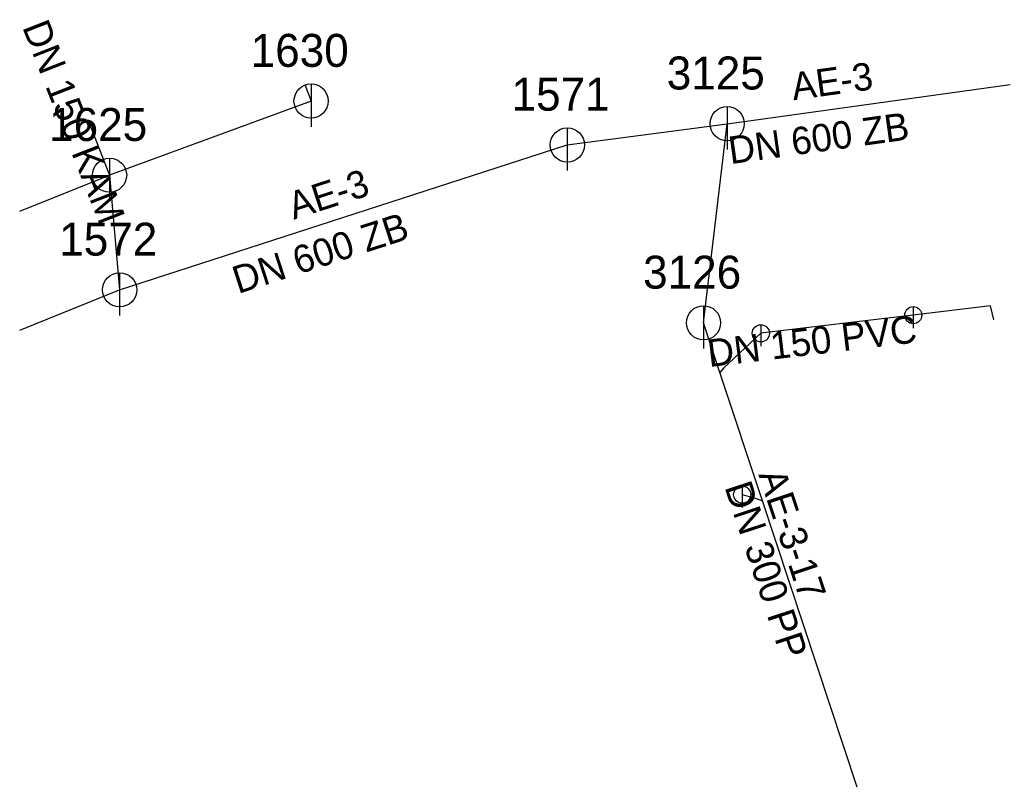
# Model space of a CAD drawing. Extents: x -494060.6 to -494002.7, y -1126804.1 to -1126759.3.
import ezdxf

# ---------------------------------------------------------------- set-up
doc = ezdxf.new("R2010")
doc.units = 0
for name, color, linetype in [('_pripojka_kanal_jednotna_priblizne_', 7, 'Continuous'), ('_pripojka_kanal_splaskova_prevzato_z_dokumentace_', 7, 'Continuous'), ('_pripojka_kanal_splaskova_priblizne_', 7, 'Continuous'), ('_stoka_jednotna_smvak_prevzato_z_dokumentace_', 7, 'Continuous'), ('_stoka_splaskova_provozovana_prevzato_z_dokumentace_', 7, 'Continuous'), ('Default', 7, 'Continuous'), ('MoLevel 119', 7, 'Continuous'), ('MoLevel 120', 7, 'Continuous'), ('MoLevel 124', 7, 'Continuous'), ('MoLevel 57', 7, 'Continuous'), ('MoLevel 60', 7, 'Continuous'), ('MoLevel 68', 7, 'Continuous'), ('MoLevel 69', 7, 'Continuous'), ('MoLevel 84', 7, 'Continuous'), ('MoLevel 85', 7, 'Continuous')]:
    doc.layers.add(name, color=color, linetype=linetype)

# ---------------------------------------------------------------- blocks, each defined once
blk = doc.blocks.new('_sachta_kanal_prip_')
at = {"layer": 'Default'}
blk.add_line((0, 0.00005), (0, -0.000075), dxfattribs=at)
blk.add_circle((0, 0), 0.00005, dxfattribs=at)
blk = doc.blocks.new('_sachta_kanal_prevzato_z_dokumentace_')
at = {"layer": 'Default'}
blk.add_line((0, 0.00005), (0, -0.000075), dxfattribs=at)
blk.add_circle((0, 0), 0.00005, dxfattribs=at)

msp = doc.modelspace()

# ---------------------------------------------------------------- linework, layer by layer
at = {"layer": '_pripojka_kanal_jednotna_priblizne_'}
for p, q in [((-494043.939, -1126763.067), (-494043.575, -1126764.029)), ((-494056.524, -1126765.36), (-494055.35, -1126768.36))]:
    msp.add_line(p, q, dxfattribs=at)
at = {"layer": '_pripojka_kanal_splaskova_prevzato_z_dokumentace_'}
for points in [[(-494017.3, -1126777.6), (-494019.47, -1126779.61), (-494019.692, -1126779.889)], [(-494018.39, -1126787.03), (-494017.57, -1126787.26), (-494017.213, -1126787.387)]]:
    msp.add_lwpolyline(points, dxfattribs=at)
at = {"layer": '_pripojka_kanal_splaskova_priblizne_'}
msp.add_line((-494008.399, -1126776.542), (-494017.3, -1126777.6), dxfattribs=at)
msp.add_lwpolyline([(-494003.685, -1126776.804), (-494003.878, -1126776.005), (-494008.399, -1126776.542)], dxfattribs=at)
at = {"layer": '_stoka_jednotna_smvak_prevzato_z_dokumentace_'}
for p, q in [((-494019.27, -1126765.35), (-494002.736, -1126763.056)), ((-494043.575, -1126764.029), (-494055.35, -1126768.36)), ((-494028.61, -1126766.59), (-494019.27, -1126765.35)), ((-494054.76, -1126775.06), (-494028.61, -1126766.59)), ((-494060.593, -1126770.47), (-494055.35, -1126768.36)), ((-494055.35, -1126768.36), (-494054.76, -1126775.06)), ((-494060.593, -1126777.424), (-494054.76, -1126775.06))]:
    msp.add_line(p, q, dxfattribs=at)
at = {"layer": '_stoka_splaskova_provozovana_prevzato_z_dokumentace_'}
msp.add_line((-494020.65, -1126776.99), (-494019.27, -1126765.35), dxfattribs=at)
msp.add_lwpolyline([(-494011.679, -1126804.129), (-494017.213, -1126787.387), (-494019.692, -1126779.889), (-494020.65, -1126776.99)], dxfattribs=at)

# ---------------------------------------------------------------- block references
at = {"layer": 'MoLevel 119', "xscale": 20000, "yscale": 20000}
for p in [(-494043.575, -1126764.029), (-494019.27, -1126765.35), (-494028.61, -1126766.59), (-494055.35, -1126768.36), (-494054.76, -1126775.06), (-494020.65, -1126776.99)]:
    msp.add_blockref('_sachta_kanal_prevzato_z_dokumentace_', p, dxfattribs=at)
at = {"layer": 'MoLevel 57', "xscale": 10000, "yscale": 10000}
for p in [(-494008.399, -1126776.542), (-494017.3, -1126777.6), (-494018.39, -1126787.03)]:
    msp.add_blockref('_sachta_kanal_prip_', p, dxfattribs=at)

# ---------------------------------------------------------------- texts
at = {"layer": 'MoLevel 120'}
for s, p in [('1630', (-494047.106, -1126762.029)), ('3125', (-494022.801, -1126763.35)), ('1571', (-494031.866, -1126764.59)), ('1625', (-494058.881, -1126766.36)), ('1572', (-494058.291, -1126773.06)), ('3126', (-494024.181, -1126774.99))]:
    msp.add_text(s, height=1.9259, dxfattribs=at).set_placement(p)
at = {"layer": 'MoLevel 124'}
msp.add_text('DN 150 KAM', height=1.6049, rotation=291.37937, dxfattribs=at).set_placement((-494060.464, -1126759.699))
at = {"layer": 'MoLevel 60'}
msp.add_text('DN 150 PVC', height=1.6049, rotation=6.77525, dxfattribs=at).set_placement((-494020.324, -1126779.575))
at = {"layer": 'MoLevel 68'}
for rotation, p in [(7.89772, (-494019.076, -1126767.716)), (17.94717, (-494047.843, -1126775.307))]:
    msp.add_text('DN 600 ZB', height=1.6049, rotation=rotation, dxfattribs=at).set_placement(p)
at = {"layer": 'MoLevel 69'}
for rotation, p in [(7.89772, (-494015.398, -1126763.985)), (17.94717, (-494044.593, -1126770.967))]:
    msp.add_text('AE-3', height=1.6049, rotation=rotation, dxfattribs=at).set_placement(p)
at = {"layer": 'MoLevel 84'}
msp.add_text('DN 300 PP', height=1.6049, rotation=288.29121, dxfattribs=at).set_placement((-494019.436, -1126786.578))
at = {"layer": 'MoLevel 85'}
msp.add_text('AE-3-17', height=1.6049, rotation=288.29121, dxfattribs=at).set_placement((-494017.456, -1126785.853))

doc.saveas('drawing.dxf')
